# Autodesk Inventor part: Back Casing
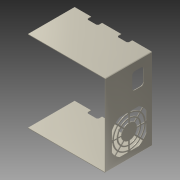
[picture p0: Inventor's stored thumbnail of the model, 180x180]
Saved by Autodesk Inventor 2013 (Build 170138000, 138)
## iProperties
Created: 2005-12
Material: Allgemein
Document SubType Name: Sheet Metal
Mass: 33.0267 g
Surface Area: 682.971 cm^2
Volume: 33.0267 cm^3
Density: 1 g/cm^3
Sheet Metal Rule: 1.0 mm
Author: Autodesk, Inc.
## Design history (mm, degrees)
node "Face1"
  sketch "Sketch3"
    geometry: L1 (85, 150)-(0, 150); L2 (0, 150)-(0, 0); L3 (85, 0)-(85, 150); L4 (0, 149)-(85, 149); L5 (0, 149)-(85, 149); L6 (85, 149)-(85, 0); L7 (85, 0)-(0, 0); L8 (0, 0)-(0, 149)
    constraints: 16 end point, 2 parallel, 2 perpendicular, 2 point on line, 1 horizontal
    dimensions: "d52" = 1 distance between parallel lines of L1 L4
node "Flange1"
node "Flange2"
cut "Cut1" dims "d21" = 1 (= Thickness), "d22" = 0
feature "Corner Chamfer1" dims "d23" = 2, "d24" = 6, angle "d25" = 45 deg
workplane "Work Plane1"
mirror "Mirror2"
cut "Cut3" dims "d49" = 1 (= Thickness), "d50" = 0
feature "Corner Round1" dims "d51" = 5
sketch "Sketch9"
  geometry: L1 (85, -146)-(85, 0) reference; L2 (12, -72.5)-(75, -72.5); L3 (75, -72.5)-(75, -135.5); L4 (75, -135.5)-(12, -135.5); L5 (12, -135.5)-(12, -72.5); L6 (0, -147.5)-(85, -147.5) reference; L7 (43.5, -72.5)-(43.5, -135.5); L8 (12, -104)-(75, -104); L9 (43.5, -104)-(75, -72.5); L10 (42.5, -104)-(44.5, -104); L11 (44.5, -104)-(44.5, -72.5); L12 (44.5, -72.5)-(42.5, -72.5); L13 (42.5, -72.5)-(42.5, -104); L14 (43.5, -103)-(75, -103); L15 (75, -103)-(75, -105); L16 (75, -105)-(43.5, -105); L17 (43.5, -105)-(43.5, -103); L18 (37.878, -108.208)-(74.293, -71.793); L19 (74.293, -71.793)-(75.707, -73.207); L20 (75.707, -73.207)-(39.292, -109.622); L21 (39.292, -109.622)-(37.878, -108.208); L22 (46, -74.104)-(46, -72.5); L23 (46, -72.5)-(60.928, -72.5); L24 (68.239, -77.847)-(63.994, -82.091); L25 (62.579, -83.507)-(58.333, -87.753); L26 (56.917, -89.168)-(52.667, -93.419); L27 (44.5, -90.036)-(44.5, -84.025); L28 (44.5, -82.023)-(44.5, -76.018); L29 (44.5, -84.025)-(44.5, -90.036); L30 (56.917, -89.168)-(52.667, -93.419); A1 r 14 centre (43.5, -104) between (52.667, -93.419) and (44.5, -90.036); A2 r 20 centre (43.5, -104) between (56.917, -89.168) and (44.5, -84.025); A3 r 22 centre (43.5, -104) between (58.333, -87.753) and (44.5, -82.023); A4 r 28 centre (43.5, -104) between (62.579, -83.507) and (44.5, -76.018); A5 r 30 centre (43.5, -104) between (46, -74.104) and (63.994, -82.091); A6 r 36 centre (43.5, -104) between (68.239, -77.847) and (60.928, -72.5); A7 r 14 centre (43.5, -104) between (52.667, -93.419) and (44.5, -90.036); A8 r 20 centre (43.5, -104) between (56.917, -89.168) and (44.5, -84.025); A9 r 22 centre (43.5, -104) between (58.333, -87.753) and (44.5, -82.023); A10 r 28 centre (43.5, -104) between (62.579, -83.507) and (44.5, -76.018); A11 r 30 centre (43.5, -104) between (63.994, -82.091) and (46, -74.104)
  constraints: 56 end point, 22 point on circle, 16 point on line, 11 centre point, 11 coincident, 9 parallel, 7 perpendicular, 6 midpoint, 3 collinear, 3 horizontal, 2 other
  dimensions: "d54" = 63 distance of L2.end L3.end; "d55" = 10 distance between parallel lines of L1 L3; "d56" = 12 distance between parallel lines of L6 L4; "d57" = 2 distance between parallel lines of L13 L11; "d58" = 2 distance of L20.end L18.start; "d59" = 28 diameter of A1; "d60" = 2 radial gap between concentric circles of A3 A2 (= d57); "d61" = 40 diameter of A2; "d62" = 2 radial gap between concentric circles of A5 A4 (= d60); "d63" = 56 diameter of A4; "d64" = 2.5 distance between parallel lines of L7 L22; "d65" = 36 radius of A6; "d66" = 6 radial gap between concentric circles of A3 A4 (derived); "d67" = 6 radial gap between concentric circles of A1 A2 (derived)
cut "Cut4" sketch "Sketch9" dims "d68" = 1 (= Thickness), "d69" = 0
workplane "Work Plane3"
workaxis "Work Axis2"
mirror "Mirror4"
pattern_circular "Circular Pattern2" dims angle "d72" = 360 deg
body "Solid1"
face "Plate1" dims "Thickness" = 1
sketch "Sketch4"
  geometry: L1 through (0, 42.5) direction (0, 1); L2 (0, 85)-(141, 85); L3 (141, 85)-(141, 0); L4 through (70.5, 0) direction (-1, 0)
  constraints: 6 end point, 1 horizontal, 1 perpendicular, 1 vertical
face "Plate2" dims "d4" = 2 (= MinimumRemnant), "d6" = 141 (computed from d16), "d7" = 90 deg, "d8" = 0.5 (= BendRadius), "SeamGap" = 0.01, "Thickness" = 1
bend "Bend1" dims "d2" = 1 (= BendReliefWidth), "d3" = 0.5 (= BendReliefDepth), "d4" = 2 (= MinimumRemnant), "d5" = 0.5 (= BendRadius), "d6" = 141 (computed from d16), "d7" = 90 deg, "d8" = 0.5 (= BendRadius), "SeamGap" = 0.01, "Thickness" = 1
sketch "Sketch5"
  geometry: L1 through (0, -42.5) direction (5.76e-32, -1); L2 (0, -85)-(-141, -85); L3 (-141, -85)-(-141, 0); L4 through (-70.5, 0) direction (1, 0)
  constraints: 6 end point, 1 horizontal, 1 perpendicular, 1 vertical
face "Plate3" dims "d11" = 2 (= MinimumRemnant), "d13" = 141 (computed from d16), "d14" = 90 deg, "d15" = 0.5 (= BendRadius), "SeamGap" = 0.01, "Thickness" = 1
bend "Bend2" dims "d9" = 1 (= BendReliefWidth), "d10" = 0.5 (= BendReliefDepth), "d11" = 2 (= MinimumRemnant), "d12" = 0.5 (= BendRadius), "d13" = 141 (computed from d16), "d14" = 90 deg, "d15" = 0.5 (= BendRadius), "SeamGap" = 0.01, "Thickness" = 1
sketch "Sketch6"
  geometry: L1 (0, 0)-(0, 85) reference; L2 (0, 85)-(-139.5, 85) reference; L3 (-105, 85)-(-85, 85); L4 (-85, 85)-(-85, 77); L5 (-85, 77)-(-105, 77); L6 (-105, 77)-(-105, 85); L7 (-50, 85)-(-30, 85); L8 (-30, 85)-(-30, 77); L9 (-30, 77)-(-50, 77); L10 (-50, 77)-(-50, 85)
  constraints: 16 end point, 4 parallel, 2 collinear, 2 horizontal, 2 perpendicular, 2 point on line
  dimensions: "d17" = 30 distance between parallel lines of L1 L8; "d18" = 35 distance between parallel lines of L10 L4; "d19" = 8 distance of L7.end L8.end; "d20" = 20 distance of L8.end L9.end
sketch "Sketch8"
  geometry: L1 (49, -13.5)-(70, -13.5); L2 (70, -13.5)-(70, -43.5); L3 (70, -43.5)-(49, -43.5); L4 (49, -43.5)-(49, -13.5); L5 (85, 1.5)-(0, 1.5) reference; L6 (85, -146)-(85, 0) reference
  constraints: 8 end point, 2 parallel, 1 horizontal, 1 perpendicular
  dimensions: "d45" = 30 distance of L1.end L2.end; "d46" = 21 distance of L1.start L1.end; "d48" = 15 distance between parallel lines of L5 L1; "d53" = 15 distance between parallel lines of L6 L2
other parameters: "BendRadius" = 0.5, "BendReliefWidth" = 1 (= Thickness), "BendReliefDepth" = 0.5 (= 0.5 x Thickness), "CornerReliefSize" = 4 (= 4 x Thickness), "MinimumRemnant" = 2 (= 2 x Thickness), "TransitionRadius" = 0.5 (= BendRadius), "d16" = 142 [user parameter; used in 2 equation terms], "d1" = 0.5 (= BendRadius), "d70" = 90 deg, "JacobiRadiusSize" = 1 (= Thickness), "GapSize" = 1 (= Thickness)
